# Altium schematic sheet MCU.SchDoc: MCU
size A3; DocumentNumber: MB1144; Revision: B-02; SheetNumber: 3; SheetTotal: 25; PageSetup: Record=PageOptions|CenterHorizontal=True|CenterVertical=True|PrintScale=1.04|XCorrection=1.00|YCorrection=1.00|PrintKind=1|BorderSize=5000000|LeftOffset=0|BottomOffset=0|Orientation=2|PaperLength=1000|PaperWidth=1000|Scale=100|PaperSource=7|PrintQuality=600|MediaType=1|DitherType=10|PaperKind=A3|PrintScaleMode=1; Project: STM32L476G-EVAL
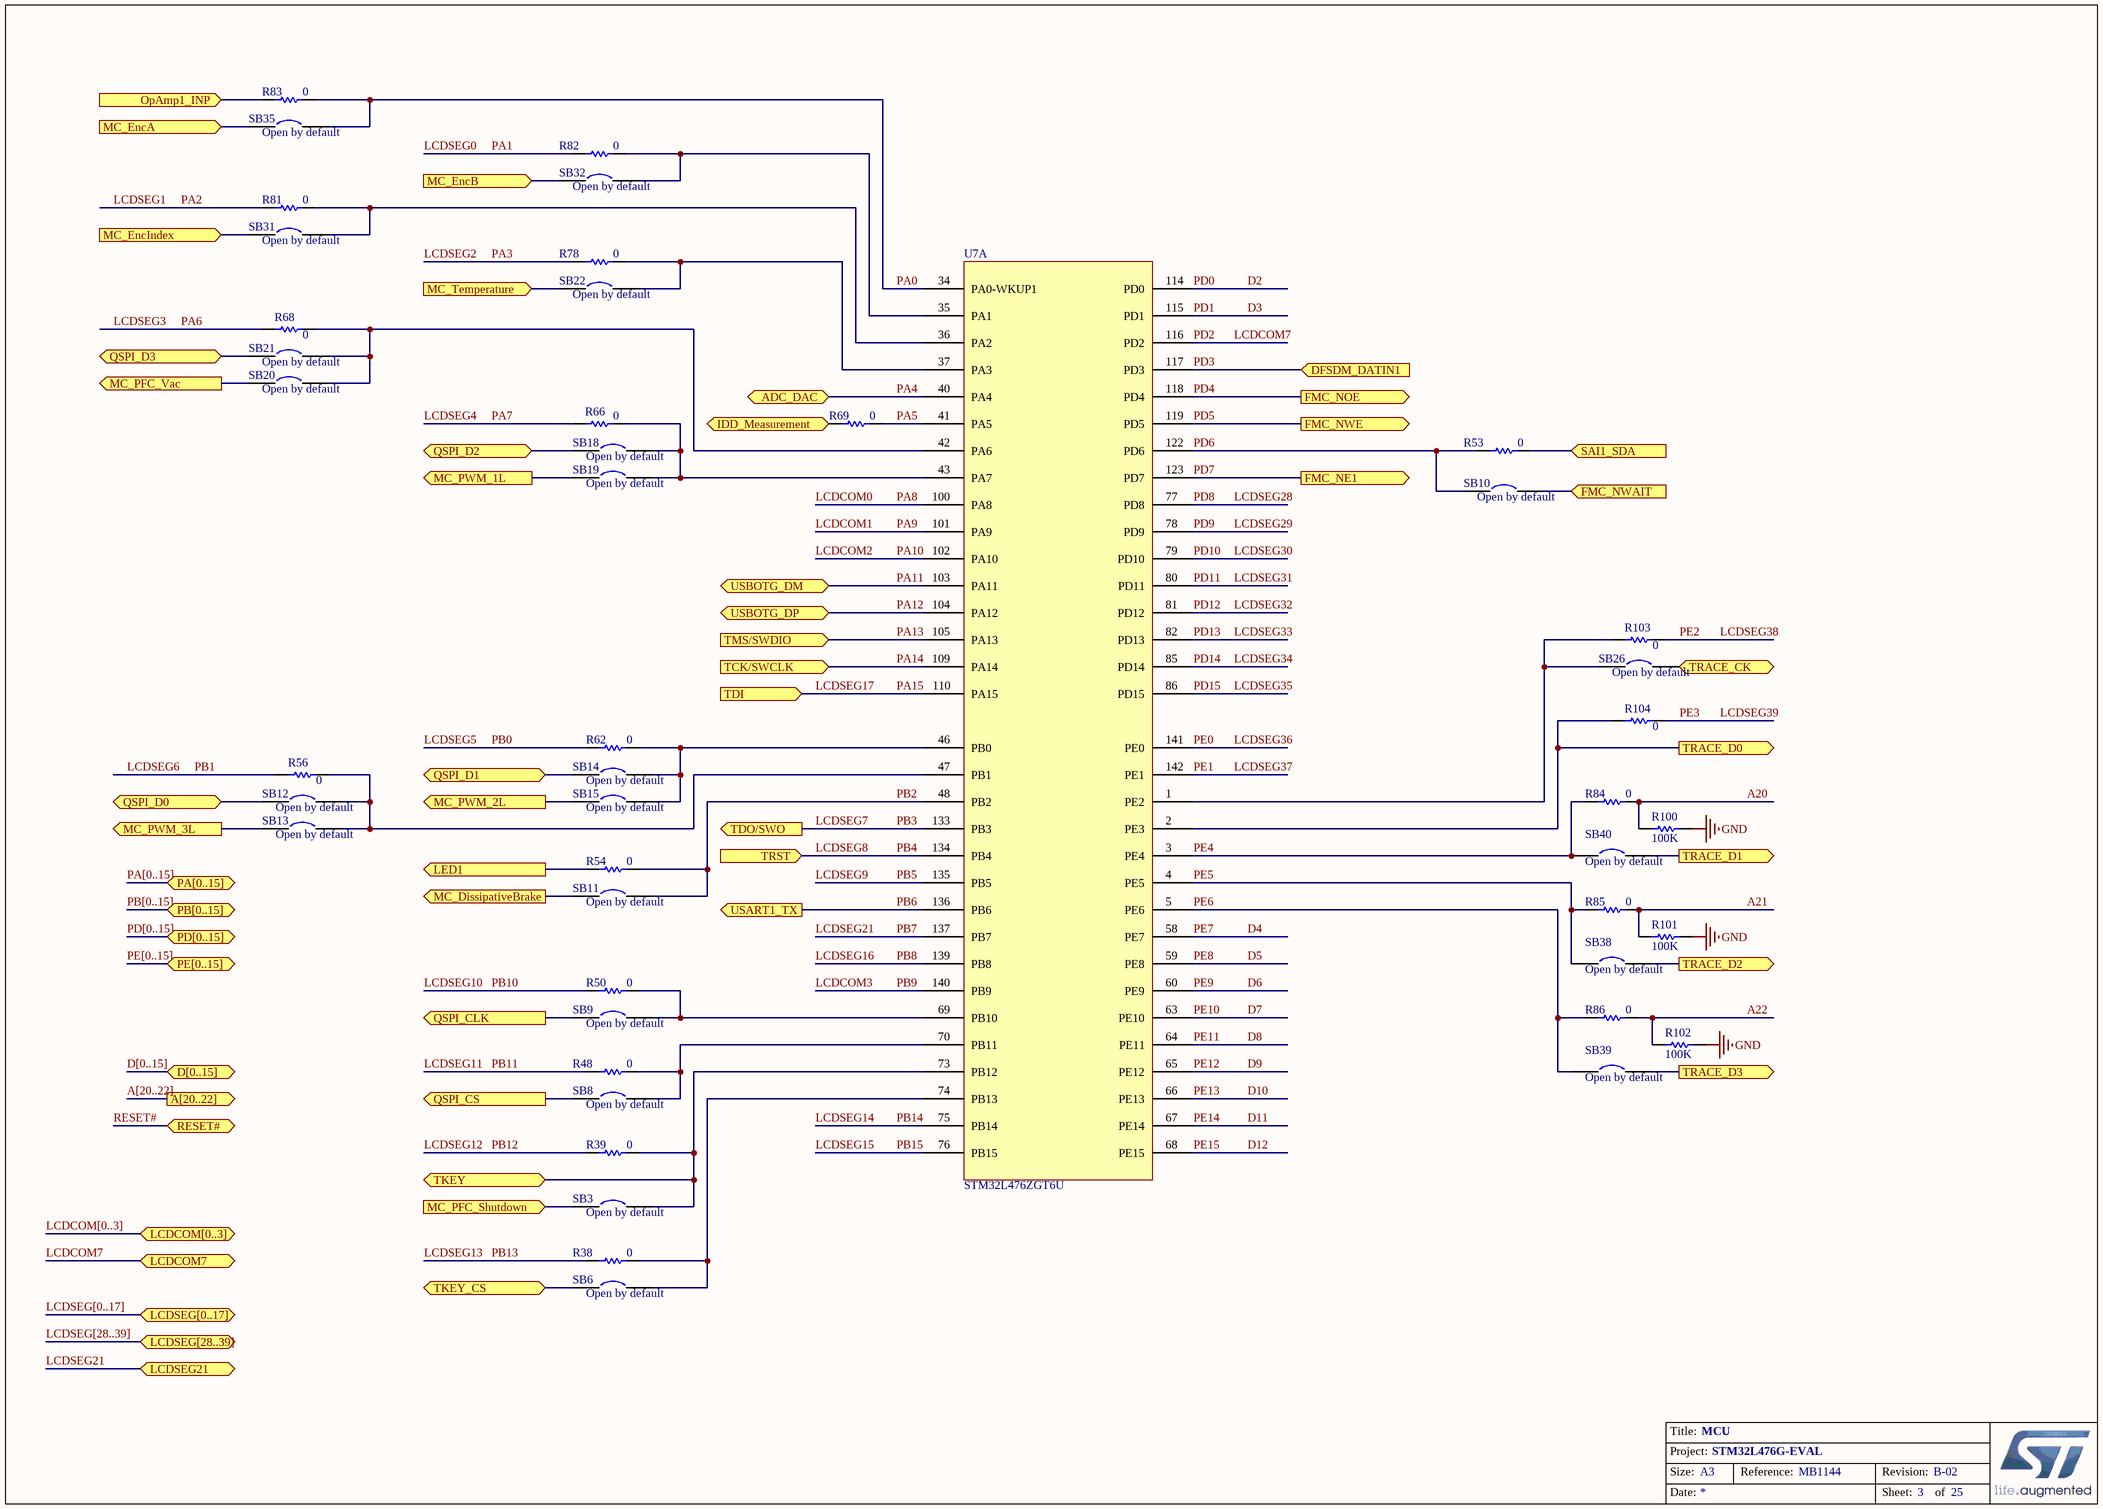
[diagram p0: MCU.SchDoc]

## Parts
R38  0  [SB_0603]
R39  0  [SB_0603]
R48  0  [SB_0603]
R50  0  [SB_0603]
R53  0  [SB_0603]
R54  0  [SB_0603]
R56  0  [SB_0603]
R62  0  [SB_0603]
R66  0  [SB_0603]
R68  0  [SB_0603]
R69  0  [0603R]
R78  0  [SB_0603]
R81  0  [SB_0603]
R82  0  [SB_0603]
R83  0  [SB_0603]
R84  0  [SB_0603]
R85  0  [SB_0603]
R86  0  [SB_0603]
R100  100K  [0402R]
R101  100K  [0402R]
R102  100K  [0402R]
R103  0  [SB_0603]
R104  0  [SB_0603]
SB3  Open by default  [SB_0603]
SB6  Open by default  [SB_0603]
SB8  Open by default  [SB_0603]
SB9  Open by default  [SB_0603]
SB10  Open by default  [SB_0603]
SB11  Open by default  [SB_0603]
SB12  Open by default  [SB_0603]
SB13  Open by default  [SB_0603]
SB14  Open by default  [SB_0603]
SB15  Open by default  [SB_0603]
SB18  Open by default  [SB_0603]
SB19  Open by default  [SB_0603]
SB20  Open by default  [SB_0603]
SB21  Open by default  [SB_0603]
SB22  Open by default  [SB_0603]
SB26  Open by default  [SB_0603]
SB31  Open by default  [SB_0603]
SB32  Open by default  [SB_0603]
SB35  Open by default  [SB_0603]
SB38  Open by default  [SB_0603]
SB39  Open by default  [SB_0603]
SB40  Open by default  [SB_0603]
U7  STM32L476ZGT6U  [TQFP144_0R5_22X22_SOCKET]  (part A of 3)

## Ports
A[20..22] (out), ADC_DAC (bidir), D[0..15] (bidir), DFSDM_DATIN1 (in), FMC_NE1 (out), FMC_NOE (out), FMC_NWAIT (in), FMC_NWE (out), IDD_Measurement (in), LCDCOM7, LCDCOM[0..3] (bidir), LCDSEG21 (bidir), LCDSEG[0..17] (bidir), LCDSEG[28..39] (bidir), LED1 (out), MC_DissipativeBrake (out), MC_EncA (in), MC_EncB (in), MC_EncIndex (in), MC_PFC_Shutdown (in), MC_PFC_Vac (out), MC_PWM_1L (out), MC_PWM_2L (out), MC_PWM_3L (out), MC_Temperature (in), OpAmp1_INP (in), PA[0..15] (bidir), PB[0..15] (bidir), PD[0..15] (bidir), PE[0..15] (bidir), QSPI_CLK (out), QSPI_CS (out), QSPI_D0 (bidir), QSPI_D1 (bidir), QSPI_D2 (bidir), QSPI_D3 (bidir), RESET# (bidir), SAI1_SDA (in), TCK/SWCLK (in), TDI (in), TDO/SWO (out), TKEY, TKEY_CS, TMS/SWDIO (in), TRACE_CK (out), TRACE_D0 (out), TRACE_D1 (out), TRACE_D2 (out), TRACE_D3 (out), TRST (in), USART1_TX (out), USBOTG_DM (bidir), USBOTG_DP (bidir)

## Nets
GND: R100.2 R101.2 R102.2
A20: R84.1 R100.1
A21: R85.1 R101.1
A22: R86.1 R102.1
D2: U7.114(PD0)  [also labelled PD0]
D3: U7.115(PD1)  [also labelled PD1]
D4: U7.58(PE7)  [also labelled PE7]
D5: U7.59(PE8)  [also labelled PE8]
D6: U7.60(PE9)  [also labelled PE9]
D7: U7.63(PE10)  [also labelled PE10]
D8: U7.64(PE11)  [also labelled PE11]
D9: U7.65(PE12)  [also labelled PE12]
D10: U7.66(PE13)  [also labelled PE13]
D11: U7.67(PE14)  [also labelled PE14]
D12: U7.68(PE15)  [also labelled PE15]
FMC_NWAIT: SB10.2 ; port FMC_NWAIT
IDD_Measurement: R69.2 ; port IDD_Measurement
LCDCOM0: U7.100(PA8)  [also labelled PA8]
LCDCOM1: U7.101(PA9)  [also labelled PA9]
LCDCOM2: U7.102(PA10)  [also labelled PA10]
LCDCOM3: U7.140(PB9)  [also labelled PB9]
LCDCOM7: U7.116(PD2) ; port LCDCOM7  [also labelled PD2]
LCDSEG0: R82.1  [also labelled PA1]
LCDSEG1: R81.1  [also labelled PA2]
LCDSEG2: R78.2  [also labelled PA3]
LCDSEG3: R68.1  [also labelled PA6]
LCDSEG4: R66.1  [also labelled PA7]
LCDSEG5: R62.1  [also labelled PB0]
LCDSEG6: R56.1  [also labelled PB1]
LCDSEG7: U7.133(PB3) ; port TDO/SWO  [also labelled PB3]
LCDSEG8: U7.134(PB4) ; port TRST  [also labelled PB4]
LCDSEG9: U7.135(PB5)  [also labelled PB5]
LCDSEG10: R50.1  [also labelled PB10]
LCDSEG11: R48.1  [also labelled PB11]
LCDSEG12: R39.2  [also labelled PB12]
LCDSEG13: R38.1  [also labelled PB13]
LCDSEG14: U7.75(PB14)  [also labelled PB14]
LCDSEG15: U7.76(PB15)  [also labelled PB15]
LCDSEG16: U7.139(PB8)  [also labelled PB8]
LCDSEG17: U7.110(PA15) ; port TDI  [also labelled PA15]
LCDSEG21: U7.137(PB7) ; port LCDSEG21  [also labelled PB7]
LCDSEG28: U7.77(PD8)  [also labelled PD8]
LCDSEG29: U7.78(PD9)  [also labelled PD9]
LCDSEG30: U7.79(PD10)  [also labelled PD10]
LCDSEG31: U7.80(PD11)  [also labelled PD11]
LCDSEG32: U7.81(PD12)  [also labelled PD12]
LCDSEG33: U7.82(PD13)  [also labelled PD13]
LCDSEG34: U7.85(PD14)  [also labelled PD14]
LCDSEG35: U7.86(PD15)  [also labelled PD15]
LCDSEG36: U7.141(PE0)  [also labelled PE0]
LCDSEG37: U7.142(PE1)  [also labelled PE1]
LCDSEG38: R103.2  [also labelled PE2]
LCDSEG39: R104.2  [also labelled PE3]
LED1: R54.2 ; port LED1
MC_DissipativeBrake: SB11.1 ; port MC_DissipativeBrake
MC_EncA: SB35.1 ; port MC_EncA
MC_EncB: SB32.1 ; port MC_EncB
MC_EncIndex: SB31.1 ; port MC_EncIndex
MC_PFC_Shutdown: SB3.1 ; port MC_PFC_Shutdown
MC_PFC_Vac: SB20.1 ; port MC_PFC_Vac
MC_PWM_1L: SB19.1 ; port MC_PWM_1L
MC_PWM_2L: SB15.1 ; port MC_PWM_2L
MC_PWM_3L: SB13.1 ; port MC_PWM_3L
MC_Temperature: SB22.1 ; port MC_Temperature
OpAmp1_INP: R83.2 ; port OpAmp1_INP
PA0: R83.1 SB35.2 U7.34(PA0-WKUP1)
PA4: U7.40(PA4) ; port ADC_DAC
PA5: R69.1 U7.41(PA5)
PA11: U7.103(PA11) ; port USBOTG_DM
PA12: U7.104(PA12) ; port USBOTG_DP
PA13: U7.105(PA13) ; port TMS/SWDIO
PA14: U7.109(PA14) ; port TCK/SWCLK
PB2: R54.1 SB11.2 U7.48(PB2)
PB6: U7.136(PB6) ; port USART1_TX
PD3: U7.117(PD3) ; port DFSDM_DATIN1
PD4: U7.118(PD4) ; port FMC_NOE
PD5: U7.119(PD5) ; port FMC_NWE
PD6: R53.1 SB10.1 U7.122(PD6)
PD7: U7.123(PD7) ; port FMC_NE1
PE4: R84.2 SB40.1 U7.3(PE4)
PE5: R85.2 SB38.1 U7.4(PE5)
PE6: R86.2 SB39.1 U7.5(PE6)
QSPI_CLK: SB9.1 ; port QSPI_CLK
QSPI_CS: SB8.1 ; port QSPI_CS
QSPI_D0: SB12.1 ; port QSPI_D0
QSPI_D1: SB14.1 ; port QSPI_D1
QSPI_D2: SB18.1 ; port QSPI_D2
QSPI_D3: SB21.1 ; port QSPI_D3
SAI1_SDA: R53.2 ; port SAI1_SDA
TKEY: R39.1 SB3.2 U7.73(PB12) ; port TKEY
TKEY_CS: SB6.1 ; port TKEY_CS
TRACE_CK: SB26.2 ; port TRACE_CK
TRACE_D0: R104.1 U7.2(PE3) ; port TRACE_D0
TRACE_D1: SB40.2 ; port TRACE_D1
TRACE_D2: SB38.2 ; port TRACE_D2
TRACE_D3: SB39.2 ; port TRACE_D3
NetR38_2: R38.2 SB6.2 U7.74(PB13)
NetR48_2: R48.2 SB8.2 U7.70(PB11)
NetR50_2: R50.2 SB9.2 U7.69(PB10)
NetR56_2: R56.2 SB12.2 SB13.2 U7.47(PB1)
NetR62_2: R62.2 SB14.2 SB15.2 U7.46(PB0)
NetR66_2: R66.2 SB18.2 SB19.2 U7.43(PA7)
NetR68_2: R68.2 SB20.2 SB21.2 U7.42(PA6)
NetR78_1: R78.1 SB22.2 U7.37(PA3)
NetR81_2: R81.2 SB31.2 U7.36(PA2)
NetR82_2: R82.2 SB32.2 U7.35(PA1)
NetR103_1: R103.1 SB26.1 U7.1(PE2)

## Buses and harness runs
bus A[20..22] = port A[20..22]
bus D[0..15] = port D[0..15]
bus LCDCOM[0..3] = port LCDCOM[0..3]
bus LCDSEG[0..17] = port LCDSEG[0..17]
bus LCDSEG[28..39] = port LCDSEG[28..39]
bus PA[0..15] = port PA[0..15]
bus PB[0..15] = port PB[0..15]
bus PD[0..15] = port PD[0..15]
bus PE[0..15] = port PE[0..15]

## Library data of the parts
R38 R48 R50 R53 R56 R62 R66 R68 R81 R82 R103 R104 = Res1: Resistor; Value: 1K; Ordered by: Subcon; ECCN_US/EU: NA
R39 R54 R69 R78 R83-R86 R100-R102 = res1: Resistor; Value: 1K; Ordered by: Subcon; ECCN_US/EU: NA
SB3 SB6 SB8-SB15 SB18-SB22 SB26 SB31 SB32 SB35 SB38-SB40 = Circuit Breaker: Ordered by: Subcon; Comments: Solder bridge; Fitted: NO; ECCN_US/EU: NA
U7 = STM32L476_TQFP144: Manuf_Part_1: STM32L476ZGT6U cut1.3; Ordered by: ST; ECCN_US/EU: 3A991A2/NEC; Assembly: MCU; Ref St: 9175195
